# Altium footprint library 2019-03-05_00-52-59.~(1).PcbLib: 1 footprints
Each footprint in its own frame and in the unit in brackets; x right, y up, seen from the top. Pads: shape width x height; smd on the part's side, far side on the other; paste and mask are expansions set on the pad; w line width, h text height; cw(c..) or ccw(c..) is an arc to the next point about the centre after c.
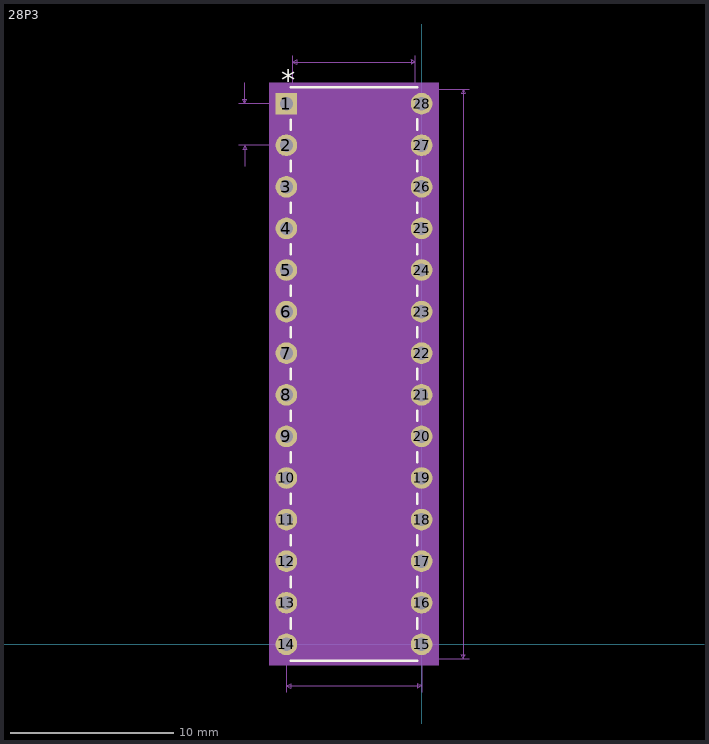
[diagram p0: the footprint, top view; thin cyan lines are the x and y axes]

## 28P3 [mil]
pads (28):
  rect 52x52 hole 32 mask+0: 1(-325,1300)
  round 52 hole 32 mask+0: 2(-325,1200) 3(-325,1100) 4(-325,1000) 5(-325,900) 6(-325,800) 7(-325,700) 8(-325,600) 9(-325,500) 10(-325,400) 11(-325,300) 12(-325,200) 13(-325,100) 14(-325,0) 15(0,0) 16(0,100) 17(0,200) 18(0,300) 19(0,400) 20(0,500) 21(0,600) 22(0,700) 23(0,800) 24(0,900) 25(0,1000) 26(0,1100) 27(0,1200) 28(0,1300)
Top Overlay:
  lines w6: -315,-40 -10,-40 ; -315,37.8 -315,62.2 ; -315,137.8 -315,162.2 ; -315,237.8 -315,262.2 ; -315,337.8 -315,362.2 ; -315,437.8 -315,462.2 ; -315,537.8 -315,562.2 ; -315,637.8 -315,662.2 ; -315,737.8 -315,762.2 ; -315,837.8 -315,862.2 ; -315,937.8 -315,962.2 ; -315,1037.8 -315,1062.2 ; -315,1137.8 -315,1162.2 ; -315,1237.8 -315,1260.9 ; -315,1340 -10,1340 ; -10,37.8 -10,62.2 ; -10,137.8 -10,162.2 ; -10,237.8 -10,262.2 ; -10,337.8 -10,362.2 ; -10,437.8 -10,462.2 ; -10,537.8 -10,562.2 ; -10,637.8 -10,662.2 ; -10,737.8 -10,762.2 ; -10,837.8 -10,862.2 ; -10,937.8 -10,962.2 ; -10,1037.8 -10,1062.2 ; -10,1137.8 -10,1162.2 ; -10,1237.8 -10,1262.2
  text "*" at -337.5,1331 h50
Mechanical 5:
  region: 41,-50 -366,-50 -366,1350 41,1350
Mechanical 7:
  lines w1: -440,1200 -325,1200 ; -440,1300 -325,1300 ; -425,1150 -425,1200 ; -425,1350 -425,1300 ; -325,-115 -325,0 ; -310,0 -310,1415 ; -162.5,-35 115,-35 ; -162.5,1335 115,1335 ; -15,0 -15,1415 ; 0,-115 0,0 ; -425,1200 -430,1190 -420,1190 -425,1200 ; -425,1300 -430,1310 -420,1310 -425,1300 ; -325,-100 0,-100 ; -325,-100 -315,-95 -315,-105 -325,-100 ; -310,1400 -15,1400 ; -310,1400 -300,1405 -300,1395 -310,1400 ; -15,1400 -25,1405 -25,1395 -15,1400 ; 0,-100 -10,-95 -10,-105 0,-100 ; 100,-35 100,1335 ; 100,-35 95,-25 105,-25 100,-35 ; 100,1335 95,1325 105,1325 100,1335
  text "Default Padstyle: EX52Y52D32P" at -525,-276 h50
  text "Pin 1 Padstyle: SX52Y52D32P" at -500,-376 h50
  text "Alt 1 Padstyle: OX60Y90D30P" at -500,-426 h50
  text "Alt 2 Padstyle: OX90Y60D30P" at -500,-476 h50
  text "0.1in/2.54mm" at -595,1237.5 h25
  text "0.325in/8.255mm" at -256.25,-145 h25
  text "0.295in/7.493mm" at -256.25,1420 h25
  text "1.37in/34.798mm" at 120,637.5 h25
Mechanical 13:
  lines w0: -174.5,1335 ccw(c-162.5,1335) -150.5,1335
  lines w1: -341,-16 -341,16 -310,16 -310,-16 -341,-16 ; -341,84 -341,116 -310,116 -310,84 -341,84 ; -341,184 -341,216 -310,216 -310,184 -341,184 ; -341,284 -341,316 -310,316 -310,284 -341,284 ; -341,384 -341,416 -310,416 -310,384 -341,384 ; -341,484 -341,516 -310,516 -310,484 -341,484 ; -341,584 -341,616 -310,616 -310,584 -341,584 ; -341,684 -341,716 -310,716 -310,684 -341,684 ; -341,784 -341,816 -310,816 -310,784 -341,784 ; -341,884 -341,916 -310,916 -310,884 -341,884 ; -341,984 -341,1016 -310,1016 -310,984 -341,984 ; -341,1084 -341,1116 -310,1116 -310,1084 -341,1084 ; -341,1184 -341,1216 -310,1216 -310,1184 -341,1184 ; -341,1284 -341,1316 -310,1316 -310,1284 -341,1284 ; -310,-35 -15,-35 -15,1335 -310,1335 -310,-35 ; -15,-16 -15,16 16,16 16,-16 -15,-16 ; -15,84 -15,116 16,116 16,84 -15,84 ; -15,184 -15,216 16,216 16,184 -15,184 ; -15,284 -15,316 16,316 16,284 -15,284 ; -15,384 -15,416 16,416 16,384 -15,384 ; -15,484 -15,516 16,516 16,484 -15,484 ; -15,584 -15,616 16,616 16,584 -15,584 ; -15,684 -15,716 16,716 16,684 -15,684 ; -15,784 -15,816 16,816 16,784 -15,784 ; -15,884 -15,916 16,916 16,884 -15,884 ; -15,984 -15,1016 16,1016 16,984 -15,984 ; -15,1084 -15,1116 16,1116 16,1084 -15,1084 ; -15,1184 -15,1216 16,1216 16,1184 -15,1184 ; -15,1284 -15,1316 16,1316 16,1284 -15,1284
  text "*" at -312.5,1275 h50
Mechanical 15:
  region: -5,-32 36,-32 36,1332 -5,1332 -5,1345 -320,1345 -320,1332 -361,1332 -361,-32 -320,-32 -320,-45 -5,-45
  lines w6: -361,-32 -361,1332 -320,1332 -320,1345 -5,1345 -5,1332 36,1332 36,-32 -5,-32 -5,-45 -320,-45 -320,-32 -361,-32
3D body: height 10, standoff 0, extent 0,0 10,10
